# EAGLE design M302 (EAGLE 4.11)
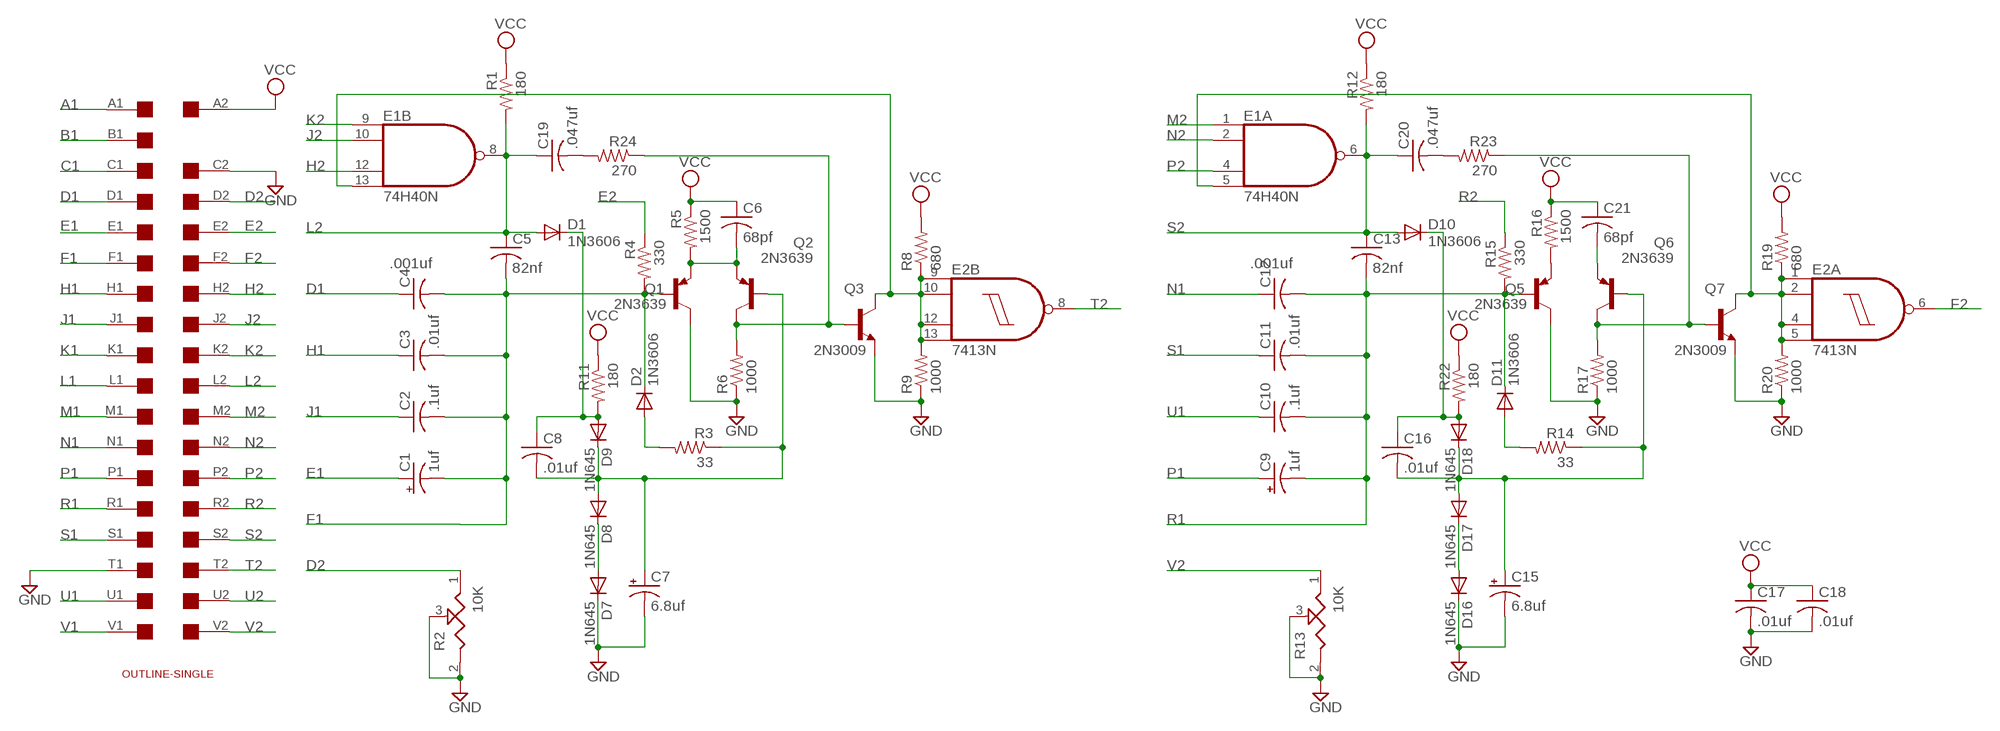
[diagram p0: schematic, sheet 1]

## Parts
C1  1uf  CPOL-USE15-5AXIAL  [E15-5]
C2  .1uf  C-US050-025X075  [C050-025X075]
C3  .01uf  C-US050-025X075  [C050-025X075]
C4  .001uf  C-US050-025X075  [C050-025X075]
C5  82nf  C-US050-025X075  [C050-025X075]
C6  68pf  C-US050-025X075  [C050-025X075]
C7  6.8uf  CPOL-USE15-5AXIAL  [E15-5]
C8  .01uf  C-US050-025X075  [C050-025X075]
C9  1uf  CPOL-USE15-5AXIAL  [E15-5]
C10  .1uf  C-US050-025X075  [C050-025X075]
C11  .01uf  C-US050-025X075  [C050-025X075]
C12  .001uf  C-US050-025X075  [C050-025X075]
C13  82nf  C-US050-025X075  [C050-025X075]
C15  6.8uf  CPOL-USE15-5AXIAL  [E15-5]
C16  .01uf  C-US050-025X075  [C050-025X075]
C17  .01uf  C-US050-025X075  [C050-025X075]
C18  .01uf  C-US050-025X075  [C050-025X075]
C19  .047uf  C-US050-025X075  [C050-025X075]
C20  .047uf  C-US050-025X075  [C050-025X075]
C21  68pf  C-US050-025X075  [C050-025X075]
D1  1N3606  1N4148  [DO35-10]
D2  1N3606  1N4148  [DO35-10]
D7  1N645  1N4148  [DO35-10]
D8  1N645  1N4148  [DO35-10]
D9  1N645  1N4148  [DO35-10]
D10  1N3606  1N4148  [DO35-10]
D11  1N3606  1N4148  [DO35-10]
D16  1N645  1N4148  [DO35-10]
D17  1N645  1N4148  [DO35-10]
D18  1N645  1N4148  [DO35-10]
E1  74H40N  74S20N  [DIL14]
E2  7413N  [DIL14]
Q1  2N3639  2N3637-PNP-TO39-EBC  [TO39]
Q2  2N3639  2N3637-PNP-TO39-EBC  [TO39]
Q3  2N3009  2N3019-NPN-TO39-EBC  [TO39]
Q5  2N3639  2N3637-PNP-TO39-EBC  [TO39]
Q6  2N3639  2N3637-PNP-TO39-EBC  [TO39]
Q7  2N3009  2N3019-NPN-TO39-EBC  [TO39]
R1  180  R-US_0207/10  [0207/10]
R2  10K  POTUS-TRIM  [PT-SPIN]
R3  33  R-US_0207/10  [0207/10]
R4  330  R-US_0207/10  [0207/10]
R5  1500  R-US_0207/10  [0207/10]
R6  1000  R-US_0207/10  [0207/10]
R8  680  R-US_0207/10  [0207/10]
R9  1000  R-US_0207/10  [0207/10]
R11  180  R-US_0207/10  [0207/10]
R12  180  R-US_0207/10  [0207/10]
R13  10K  POTUS-TRIM  [PT-SPIN]
R14  33  R-US_0207/10  [0207/10]
R15  330  R-US_0207/10  [0207/10]
R16  1500  R-US_0207/10  [0207/10]
R17  1000  R-US_0207/10  [0207/10]
R19  680  R-US_0207/10  [0207/10]
R20  1000  R-US_0207/10  [0207/10]
R22  180  R-US_0207/10  [0207/10]
R23  270  R-US_0207/10  [0207/10]
R24  270  R-US_0207/10  [0207/10]
U$1  SINGLE  [EDGE-CON2]
U$2  OUTLINE-SINGLE  [SINGLE]

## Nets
A1: U$1.A1
B1: U$1.B1
C1: U$1.C1
D1: C4.1 U$1.D1
D2: R2.1 U$1.D2
E1: C1.+ U$1.E1
E2: R4.1 U$1.E2
F1: C1.- C2.2 C3.2 C4.2 C5.2 D2.C Q1.2(B) R4.2 U$1.F1
F2: E2.6(A:O) U$1.F2
GND [power]: C7.- C15.- C17.2 C18.2 D7.C D16.C Q1.3(C) Q3.1(E) Q5.3(C) Q7.1(E) R2.2 R2.3 R6.1 R9.1 R13.2 R13.3 R17.1 R20.1 U$1.C2 U$1.T1
H1: C3.1 U$1.H1
H2: E1.12(B:I2) U$1.H2
J1: C2.1 U$1.J1
J2: E1.10(B:I1) U$1.J2
K1: U$1.K1
K2: E1.9(B:I0) U$1.K2
L1: U$1.L1
L2: C5.1 C19.1 D1.A E1.8(B:O) R1.2 U$1.L2
M1: U$1.M1
M2: E1.1(A:I0) U$1.M2
N1: C12.1 U$1.N1
N2: E1.2(A:I1) U$1.N2
N$1: C8.1 D1.C D9.A R11.2
N$2: E1.13(B:I3) E2.9(B:I0) E2.10(B:I1) E2.12(B:I2) E2.13(B:I3) Q3.3(C) R8.1 R9.2
N$3: C6.2 Q1.1(E) Q2.1(E) R5.2
N$4: E1.5(A:I3) E2.1(A:I0) E2.2(A:I1) E2.4(A:I2) E2.5(A:I3) Q7.3(C) R19.1 R20.2
N$5: C7.+ C8.2 D8.A D9.C Q2.2(B) R3.1
N$6: Q6.3(C) Q7.2(B) R17.2 R23.1
N$7: D2.A R3.2
N$8: Q2.3(C) Q3.2(B) R6.2 R24.1
N$9: D7.A D8.C
N$10: Q5.1(E) R16.2
N$11: C21.2 Q6.1(E)
N$12: C15.+ C16.2 D17.A D18.C Q6.2(B) R14.1
N$13: D11.A R14.2
N$14: C19.2 R24.2
N$15: C20.2 R23.2
N$16: C16.1 D10.C D18.A R22.2
N$20: D16.A D17.C
P1: C9.+ U$1.P1
P2: E1.4(A:I2) U$1.P2
R1: C9.- C10.2 C11.2 C12.2 C13.2 D11.C Q5.2(B) R15.2 U$1.R1
R2: R15.1 U$1.R2
S1: C11.1 U$1.S1
S2: C13.1 C20.1 D10.A E1.6(A:O) R12.2 U$1.S2
T2: E2.8(B:O) U$1.T2
U1: C10.1 U$1.U1
U2: U$1.U2
V1: U$1.V1
V2: R13.1 U$1.V2
VCC [power]: C6.1 C17.1 C18.1 C21.1 R1.1 R5.1 R8.2 R11.1 R12.1 R16.1 R19.2 R22.1 U$1.A2
Unconnected: U$1.B2

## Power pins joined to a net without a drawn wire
GND: E1.7(P:GND) E2.7(P:GND)
VCC: E1.14(P:VCC) E2.14(P:VCC)

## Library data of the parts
C1 C7 C9 C15 = rcl:CPOL-US: POLARIZED CAPACITOR, American symbol
C2-C6 C8 C10-C13 C16-C21 = rcl:C-US: CAPACITOR, American symbol
D1 D2 D7-D11 D16-D18 = diode:1N4148: DIODE
E1 = 74xx-us:74*20: Dual 4-input NAND gate
E2 = 74xx-us:74*13: Dual 4-input NAND schmitt trigger
Q1 Q2 Q5 Q6 = transistor:*-PNP-: PNP Transistror
Q3 Q7 = transistor:*-NPN-: NPN Transistror
R1 R3-R6 R8 R9 R11 R12 R14-R17 R19 R20 R22-R24 = rcl:R-US_: RESISTOR, American symbol
R2 R13 = discrete:POTUS-TRIM
U$1 = dec-con:SINGLE: Single-Height DEC board
U$2 = dec-con:OUTLINE-*: Board outlines for DEC boards.

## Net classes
1 power: width 0.508 mm, drill 0.508 mm

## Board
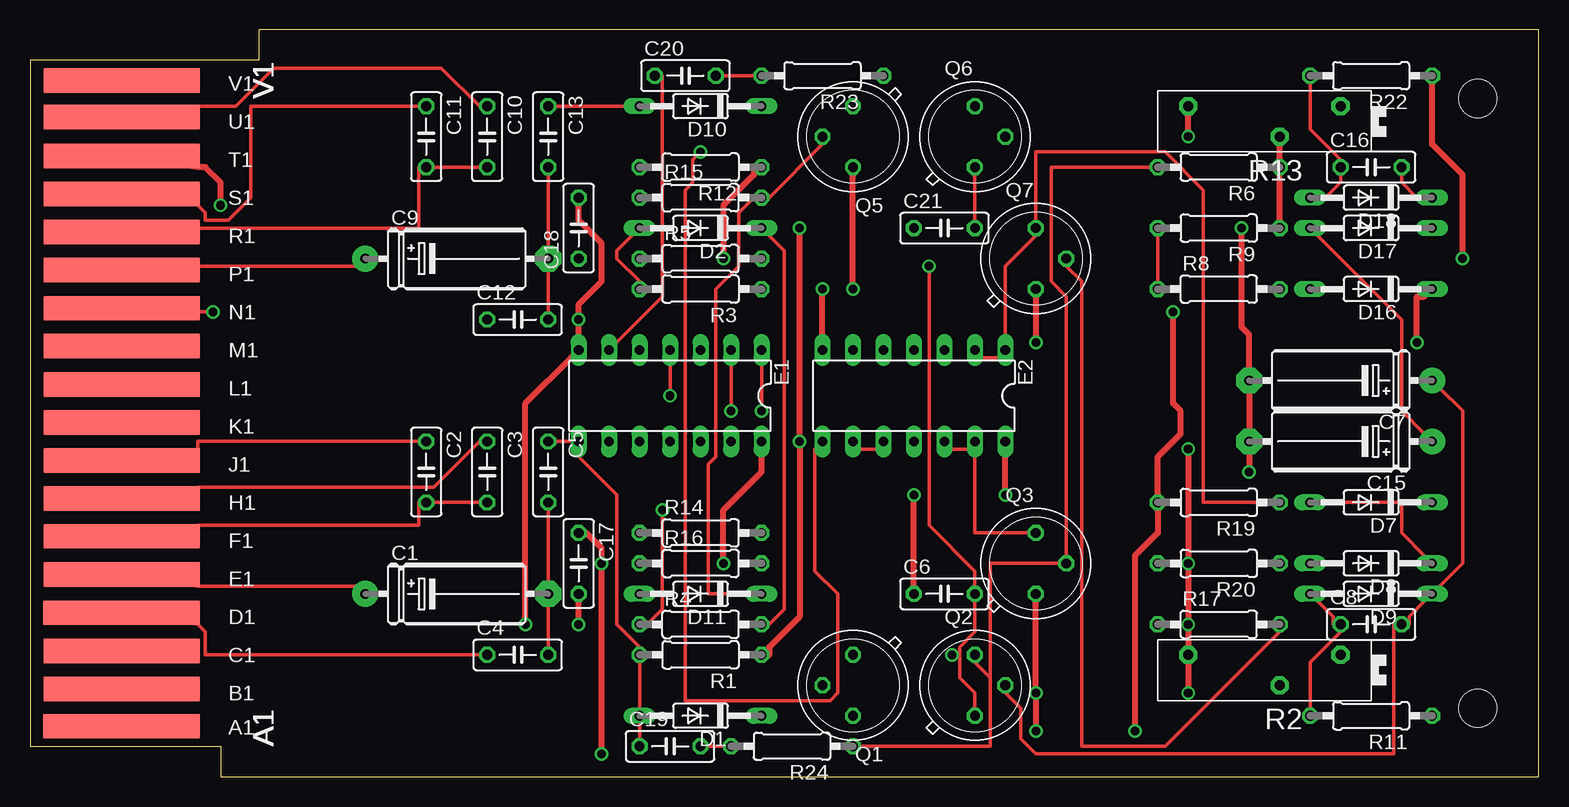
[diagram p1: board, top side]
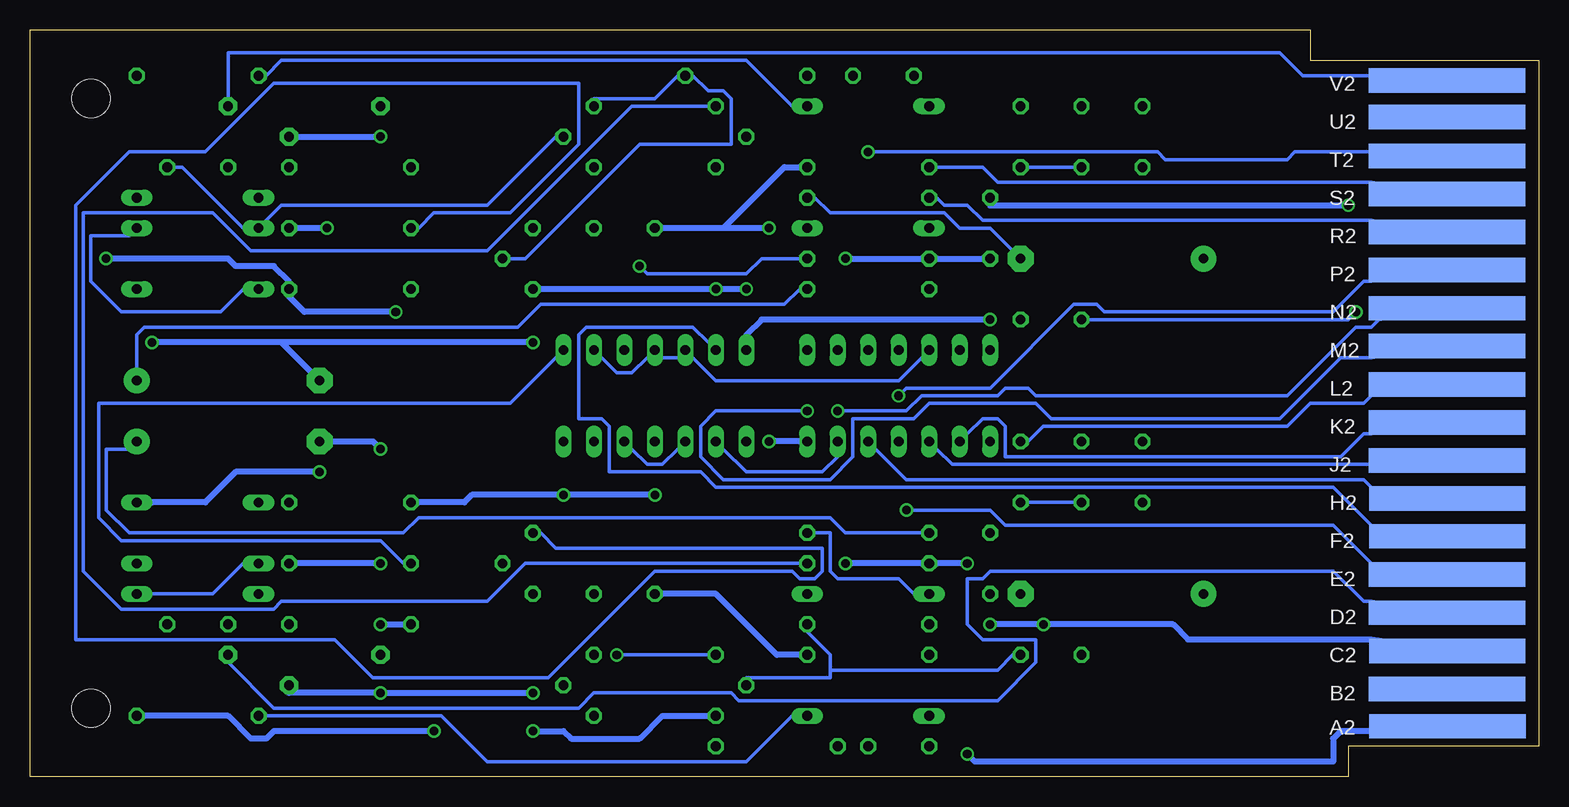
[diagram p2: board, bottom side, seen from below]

Size 125.73 x 62.23 mm. Coordinates in mm from the lower left corner, seen from the top.
Copper layers (1*16): Top 0.035mm / dielectric 1.5mm / Bottom 0.035mm
Design rules "10mils": minimum track width 12mil, minimum drill 28mil, track to track 10mil, track to pad 10mil, pad to pad 10mil, via to via 10mil, smd to smd 10mil, copper to edge 40mil, drill to drill 10mil, minimum pad ring 10mil, minimum via ring 8mil, stop-mask expansion 0mil, vias tented up to drill 0mil, thermal gap 10mil

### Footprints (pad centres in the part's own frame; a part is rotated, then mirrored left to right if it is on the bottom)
E15-5 = drill 0.813 pad 2.159 round: + -7.62,0 | drill 0.813 pad 2.159 octagon: - 7.62,0
C050-025X075 = drill 0.813 octagon: 1 -2.54,0; 2 2.54,0
DO35-10 = drill 0.813 long: A 5.08,0; C -5.08,0
DIL14 = drill 0.813 long: 1 -7.62,-3.81; 2 -5.08,-3.81; 3 -2.54,-3.81; 4 0,-3.81; 5 2.54,-3.81; 6 5.08,-3.81; 7 7.62,-3.81; 8 7.62,3.81; 9 5.08,3.81; 10 2.54,3.81; 11 0,3.81; 12 -2.54,3.81; 13 -5.08,3.81; 14 -7.62,3.81
TO39 = drill 0.813 octagon: 1 0,-2.54; 2 2.54,0; 3 0,2.54
0207/10 = drill 0.813 octagon: 1 -5.08,0; 2 5.08,0
PT-SPIN = drill 0.813 pad 1.524 octagon: 1 -6.35,-1.27; 2 6.35,-1.27; 3 -1.27,1.27
EDGE-CON2 = smd 13.017 x 2.032: A1 7.633,4.207; B1 7.639,7.327; C1 7.636,10.489; D1 7.633,13.665; E1 7.642,16.84; F1 7.642,20.041; H1 7.642,23.19; J1 7.642,26.34; K1 7.642,29.515; L1 7.642,32.69; M1 7.642,35.89; N1 7.642,39.04; P1 7.642,42.24; R1 7.642,45.39; S1 7.642,48.565; T1 7.642,51.74; U1 7.642,54.966; V1 7.642,58.026 | smd 13.017 x 2.032 bottom: A2 7.614,4.207; B2 7.642,7.328; C2 7.617,10.49; D2 7.642,13.665; E2 7.642,16.84; F2 7.617,20.041; H2 7.617,23.19; J2 7.642,26.34; K2 7.642,29.515; L2 7.642,32.69; M2 7.642,35.89; N2 7.642,39.04; P2 7.642,42.24; R2 7.642,45.39; S2 7.642,48.565; T2 7.642,51.74; U2 7.642,54.966; V2 7.642,58.026
SINGLE = hole 3.175: 120.65,56.515; 120.65,5.715

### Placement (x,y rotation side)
C1  35.56,15.24 0 top
C2  33.02,25.4 270 top
C3  38.1,25.4 270 top
C4  40.64,10.16 0 top
C5  43.18,25.4 270 top
C6  76.2,15.24 0 top
C7  109.22,33.02 180 top
C8  111.76,12.7 0 top
C9  35.56,43.18 0 top
C10  38.1,53.34 270 top
C11  33.02,53.34 270 top
C12  40.64,38.1 0 top
C13  43.18,53.34 270 top
C15  109.22,27.94 180 top
C16  111.76,50.8 0 top
C17  45.72,17.78 270 top
C18  45.72,45.72 90 top
C19  53.34,2.54 0 top
C20  54.61,58.42 0 top
C21  76.2,45.72 0 top
D1  55.88,5.08 180 top
D2  55.88,45.72 180 top
D7  111.76,22.86 180 top
D8  111.76,17.78 180 top
D9  111.76,15.24 180 top
D10  55.88,55.88 180 top
D11  55.88,15.24 180 top
D16  111.76,40.64 180 top
D17  111.76,45.72 180 top
D18  111.76,48.26 180 top
E1  53.34,31.75 180 top
E2  73.66,31.75 180 top
Q1  68.58,7.62 180 top
Q2  78.74,7.62 0 top
Q3  83.82,17.78 0 top
Q5  68.58,53.34 180 top
Q6  78.74,53.34 0 top
Q7  83.82,43.18 0 top
R1  55.88,10.16 180 top
R2  102.87,8.89 180 top
R3  55.88,40.64 180 top
R4  55.88,12.7 0 top
R5  55.88,43.18 0 top
R6  99.06,50.8 180 top
R8  99.06,40.64 0 top
R9  99.06,45.72 180 top
R11  111.76,5.08 180 top
R12  55.88,50.8 180 top
R13  102.87,54.61 180 top
R14  55.88,20.32 0 top
R15  55.88,48.26 0 top
R16  55.88,17.78 0 top
R17  99.06,12.7 0 top
R19  99.06,22.86 180 top
R20  99.06,17.78 180 top
R22  111.76,58.42 180 top
R23  66.04,58.42 180 top
R24  63.5,2.54 180 top
U$1  0,0 0 top
U$2  0,0 0 top

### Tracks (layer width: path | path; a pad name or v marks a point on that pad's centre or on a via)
D1
  Top 0.305: C4.1 37.47,10.16 14.61,10.16 14.61,12.06 13.97,12.7 U$1.D1
D2
  Bottom 0.305: R2.1 109.22,9.53 105.41,5.71 80.01,5.71 78.74,6.99 67.31,6.99 66.68,6.35 45.09,6.35 41.91,9.53 41.91,11.43 46.36,11.43 47.63,12.7 47.63,16.51 46.36,16.51 45.72,17.14 17.15,17.14 14.61,14.61 13.97,14.61 U$1.D2
E1
  Top 0.305: C1.+ 27.31,15.88 13.97,15.88 U$1.E1
E2  (via drill 0.71)
  Top 0.305: v52.71,22.23 52.71,13.97 51.44,12.7 R4.1
  Bottom 0.305: v52.71,22.23 45.72,22.23 44.45,20.95 17.15,20.95 13.97,17.78 U$1.E2
F1
  Top 0.305: C4.2 43.18,10.79 43.18,14.61 C1.- 43.18,15.88 43.18,22.23 C5.2 | C3.2 37.47,22.86 33.66,22.86 C2.2 32.39,22.86 32.39,20.95 13.97,20.95 U$1.F1 | D2.C 61.6,45.09 62.87,43.81 62.87,13.97 61.6,12.7 R4.2
  Bottom 0.305: C5.2 42.55,22.86 38.74,22.86 C3.2 | 59.06,8.89 59.06,8.26 66.04,8.26 Q1.2 | 59.06,8.89 59.06,10.16 60.96,12.06 R4.2 | 59.06,8.89 45.09,8.89 43.82,10.16 C4.2
F2
  Bottom 0.305: E2.6 69.22,36.2 70.49,37.47 79.38,37.47 80.01,36.83 80.01,29.84 78.11,29.84 77.47,29.21 77.47,25.4 69.85,25.4 68.58,24.13 17.15,24.13 13.97,20.95 U$1.F2
GND  (via drill 0.71)
  Top 0.508: v96.52,6.99 96.52,9.53 R2.2 96.52,10.79 v96.52,12.7 v96.52,17.78 v96.52,27.3 | v83.82,3.81 v83.82,6.99 83.82,14.61 Q3.1 | v66.04,40.64 66.04,36.83 E2.7 | v68.58,40.64 68.58,50.16 Q5.3 | v101.6,25.4 101.6,27.3 C15.- 101.6,28.57 101.6,32.38 C7.- 101.6,33.66 101.6,36.83 100.97,37.47 v100.97,45.72 | R9.1 104.14,46.35 104.14,50.16 R6.1 104.14,51.44 104.14,52.7 R13.3 | v96.52,53.34 96.52,55.24 R13.2 | v115.57,36.2 115.57,40.01 116.21,40.01 D16.C | v83.82,36.2 83.82,40.01 Q7.1 | v45.72,12.7 45.72,14.61 C17.2 | v15.88,47.62 15.88,49.53 14.61,50.8 13.97,50.8 U$1.T1 | C18.2 45.72,47.62 45.72,46.35 47.63,44.45 47.63,41.27 45.72,39.37 v45.72,38.1 45.72,36.83 E1.7 45.09,34.92 41.28,31.11 v41.28,12.7
  Bottom 0.508: v96.52,12.7 94.62,12.7 R17.1 | v96.52,17.78 103.51,17.78 R20.1 | R2.3 104.14,6.99 v96.52,6.99 v83.82,6.99 | v83.82,3.81 81.28,3.81 80.65,3.17 74.93,3.17 73.03,5.08 69.22,5.08 Q1.3 | v66.04,40.64 v68.58,40.64 83.19,40.64 Q7.1 | v101.6,25.4 108.59,25.4 111.13,22.86 115.57,22.86 D7.C | v96.52,53.34 103.51,53.34 R13.3 | 104.78,36.2 v115.57,36.2 | 104.78,36.2 102.24,33.66 C7.- | v100.97,45.72 103.51,45.72 R9.1 | v83.82,36.2 104.78,36.2 | v96.52,27.3 97.16,27.94 100.97,27.94 C15.- | v45.72,12.7 v41.28,12.7 30.48,12.7 29.21,11.43 13.97,11.43 U$1.C2 | v15.88,47.62 45.72,47.62 C18.2 | v45.72,38.1 64.77,38.1 66.04,36.83 E2.7
H1
  Top 0.305: C3.1 37.47,27.94 33.66,24.13 13.97,24.13 U$1.H1
H2
  Bottom 0.305: E1.12 55.25,27.3 52.71,24.77 14.61,24.77 13.97,24.13 U$1.H2
J1
  Top 0.305: C2.1 32.39,27.94 13.97,27.94 13.97,27.3 U$1.J1
J2
  Bottom 0.305: E1.10 50.17,27.3 48.9,26.04 13.97,26.04 U$1.J2
K2
  Bottom 0.305: E1.9 47.63,28.57 46.36,29.84 45.09,29.84 44.45,29.21 44.45,26.67 16.51,26.67 14.61,28.57 13.97,28.57 U$1.K2
L2
  Top 0.305: C5.1 43.82,27.94 45.09,27.94 E1.8 45.72,26.67 48.9,23.5 48.9,12.7 50.8,10.79 R1.2 50.8,9.53 50.8,5.71 D1.A 50.8,4.45 50.8,3.17 C19.1
  Bottom 0.305: U$1.L2 13.97,31.75 14.61,31.11 19.05,31.11 20.96,29.21 41.28,29.21 42.55,27.94 C5.1
M2  (via drill 0.71)
  Top 0.305: v60.96,30.48 60.96,34.29 E1.1
  Bottom 0.305: v60.96,30.48 68.58,30.48 69.85,29.21 69.85,26.67 67.95,24.77 59.06,24.77 57.15,26.67 57.15,29.84 52.07,29.84 50.8,31.11 41.91,31.11 40.64,29.84 21.59,29.84 16.51,34.92 13.97,34.92 U$1.M2
N1  (via drill 0.71)
  Top 0.305: v15.24,38.73 13.97,38.73 U$1.N1
  Bottom 0.305: v15.24,38.73 15.88,38.1 37.47,38.1 C12.1
N2  (via drill 0.71)
  Top 0.305: v58.42,30.48 58.42,34.29 E1.2
  Bottom 0.305: v58.42,30.48 52.71,30.48 51.44,31.75 45.09,31.75 44.45,32.38 42.55,32.38 41.91,31.75 20.96,31.75 15.24,37.47 13.97,37.47 13.34,38.1 U$1.N2
N$1
  Top 0.305: D9.A 107.32,14.61 108.59,13.34 108.59,12.7 C8.1 109.22,12.06 106.68,9.53 106.68,5.71 R11.2
  Bottom 0.305: D1.C 62.23,5.08 66.04,1.27 87.63,1.27 91.44,5.08 106.05,5.08 R11.2
N$2
  Top 0.305: E2.10 70.49,27.3 69.22,27.3 E2.9 | R8.1 93.98,41.27 93.98,45.09 R9.2 | E2.12 76.84,27.3 78.11,27.3 E2.13 78.74,26.67 78.74,20.32 83.19,20.32 Q3.3
  Bottom 0.305: E1.13 58.42,26.67 59.69,25.4 66.04,25.4 67.95,27.3 E2.9 | R9.2 93.35,45.72 92.08,46.99 85.73,46.99 80.01,52.7 80.01,57.78 105.41,57.78 111.13,52.07 117.48,52.07 121.92,47.62 121.92,11.43 100.33,11.43 97.16,8.26 82.55,8.26 73.66,17.14 62.23,17.14 61.6,16.51 60.33,16.51 59.69,17.14 59.69,19.05 81.92,19.05 83.19,20.32 Q3.3 | E2.10 71.76,27.3 73.03,26.04 74.3,26.04 75.57,27.3 E2.12
N$3  (via drill 0.71)
  Top 0.305: 77.47,10.16 77.47,8.26 78.74,6.99 78.74,5.71 Q2.1 | 77.47,10.16 77.47,10.79 78.74,12.06 78.74,14.61 C6.2 78.74,15.88 78.74,17.14 74.93,20.95 v74.93,42.55 | v76.84,10.16 77.47,10.16
  Bottom 0.305: v76.84,10.16 69.22,10.16 Q1.1 | v74.93,42.55 74.3,41.91 66.04,41.91 64.77,43.18 61.6,43.18 R5.2
N$4
  Top 0.305: E2.2 79.38,34.92 80.65,34.92 E2.1 81.28,36.83 81.28,42.55 83.82,45.09 Q7.3 83.82,46.35 83.82,52.07 94.62,52.07 97.79,48.9 97.79,22.86 103.51,22.86 R19.1
  Bottom 0.305: E1.5 51.44,34.92 53.34,33.02 68.58,33.02 70.49,34.92 E2.5 71.76,34.92 73.03,34.92 E2.4 74.3,34.92 75.57,33.66 76.84,33.66 78.11,34.92 E2.2 | R20.2 94.62,17.78 96.52,19.68 118.11,19.68 120.02,21.59 120.02,31.11 85.73,31.11 81.92,34.92 E2.1
N$5
  Top 0.305: Q2.2 81.28,6.99 82.55,5.71 82.55,3.17 83.82,1.91 113.67,1.91 113.67,12.7 C8.2 114.94,12.7 114.94,13.34 116.21,14.61 D9.C 117.48,15.88 119.38,17.78 119.38,30.48 117.48,32.38 C7.+
  Bottom 0.305: D8.A 107.95,17.78 110.49,15.24 115.57,15.24 D9.C | R3.1 61.6,40.64 62.87,39.37 83.19,39.37 85.09,37.47 116.21,37.47 116.84,36.83 116.84,33.66 C7.+
N$6
  Top 0.305: R17.2 104.14,12.06 94.62,2.54 87.63,2.54 87.63,41.27 86.36,42.55 Q7.2
  Bottom 0.305: Q6.3 78.74,56.52 73.66,56.52 71.76,58.42 R23.1 70.49,58.42 69.22,57.15 67.95,57.15 67.31,56.52 67.31,52.7 74.93,52.7 84.46,43.18 85.73,43.18 Q7.2
N$7
  Top 0.305: R3.2 50.8,41.27 48.9,43.18 48.9,43.81 50.17,45.09 D2.A
N$8
  Top 0.305: 80.01,8.26 80.01,2.54 69.22,2.54 R24.1 | 80.01,8.26 78.74,9.53 Q2.3 | 80.01,8.26 80.01,17.78 85.73,17.78 Q3.2 86.36,18.41 86.36,40.01 85.09,41.27 85.09,50.8 93.35,50.8 R6.2
N$9
  Top 0.305: D7.A 107.95,22.86 114.3,22.86 114.3,20.32 116.21,18.41 D8.C
N$10
  Bottom 0.305: R16.2 61.6,17.78 84.46,17.78 87.63,14.61 104.78,14.61 105.41,13.97 118.11,13.97 121.29,17.14 121.29,46.99 110.49,46.99 107.32,43.81 87.63,43.81 75.57,55.88 69.22,55.88 Q5.1
N$11
  Top 0.305: C21.2 78.74,46.35 78.74,50.16 Q6.1
N$12
  Top 0.305: D18.C 115.57,48.26 114.3,49.53 114.3,50.16 C16.2 | D17.A 107.32,45.09 114.3,38.1 114.3,30.48 116.21,28.57 C15.+
  Bottom 0.305: C16.2 113.67,50.8 113.03,50.8 107.95,45.72 D17.A 106.05,46.35 104.78,47.62 87.63,47.62 81.92,53.34 Q6.2 | R14.1 51.44,20.32 57.79,20.32 59.06,21.59 93.35,21.59 94.62,20.32 117.48,20.32 119.38,22.23 119.38,27.3 117.48,27.3 C15.+
N$13
  Bottom 0.305: D11.A 52.07,15.24 53.34,16.51 58.42,16.51 59.06,17.14 59.06,20.32 60.33,20.32 R14.2
N$14
  Top 0.305: C19.2 56.52,2.54 57.79,2.54 R24.2
N$15
  Top 0.305: C20.2 57.79,58.42 60.33,58.42 R23.2
N$16
  Top 0.305: D18.A 107.95,48.26 109.22,49.53 109.22,50.16 C16.1 109.22,51.44 106.68,53.98 106.68,57.78 R22.2
  Bottom 0.305: D10.C 62.23,55.88 66.04,59.69 104.78,59.69 106.05,58.42 R22.2
N$20
  Bottom 0.305: D16.A 107.95,40.64 109.86,38.73 118.11,38.73 120.65,41.27 120.65,45.09 117.48,45.09 D17.C
P1
  Top 0.305: C9.+ 27.31,42.55 13.97,42.55 U$1.P1
P2  (via drill 0.71)
  Top 0.305: v53.34,31.75 53.34,34.29 E1.4
  Bottom 0.305: v53.34,31.75 52.71,32.38 45.72,32.38 38.74,39.37 36.83,39.37 36.2,38.73 17.15,38.73 14.61,41.27 13.97,41.27 U$1.P2
R1
  Top 0.305: C12.2 43.18,38.73 43.18,42.55 C9.- 43.18,43.81 43.18,50.16 C13.2 | C10.2 37.47,50.8 33.66,50.8 C11.2 32.39,50.8 32.39,45.72 13.97,45.72 U$1.R1 | D11.C 59.69,15.24 56.52,15.24 56.52,26.04 57.15,26.67 57.15,40.64 59.06,42.55 59.06,46.99 60.33,48.26 R15.2 61.6,48.26 66.04,52.7 Q5.2
  Bottom 0.305: C13.2 42.55,50.8 38.74,50.8 C10.2 | C9.- 43.82,43.81 45.72,45.72 48.26,45.72 49.53,46.99 59.06,46.99 60.33,48.26 R15.2
R2
  Bottom 0.305: R15.1 50.17,48.26 49.53,47.62 47.63,47.62 46.36,46.35 13.97,46.35 U$1.R2
S1
  Top 0.305: C11.1 32.39,55.88 18.42,55.88 18.42,48.26 16.51,46.35 14.61,46.35 14.61,46.99 13.97,47.62 U$1.S1
S2
  Top 0.305: C13.1 43.82,55.88 49.53,55.88 D10.A 52.07,55.88 52.71,55.88 | 52.71,55.88 52.71,58.42 C20.1 | 52.71,50.8 52.71,55.88 | 52.71,50.8 52.71,40.01 48.9,36.2 E1.6 | 52.71,50.8 51.44,50.8 R12.2
  Bottom 0.305: U$1.S2 13.97,49.53 45.09,49.53 46.36,50.8 50.17,50.8 R12.2
T2  (via drill 0.71)
  Top 0.305: v55.88,52.07 55.25,51.44 55.25,49.53 54.61,48.9 54.61,6.35 66.68,6.35 67.31,6.99 67.31,15.24 65.41,17.14 65.41,27.3 E2.8
  Bottom 0.305: v55.88,52.07 31.75,52.07 31.12,51.44 20.96,51.44 20.32,52.07 13.97,52.07 U$1.T2
U1
  Top 0.305: C10.1 37.47,55.88 34.29,59.05 20.32,59.05 17.15,55.88 13.97,55.88 U$1.U1
V2
  Bottom 0.305: R13.1 109.22,56.52 109.22,60.33 21.59,60.33 19.69,58.42 13.97,58.42 U$1.V2
VCC  (via drill 0.71)
  Top 0.508: v47.63,1.91 v47.63,17.78 47.63,19.05 46.36,20.32 C17.1 | v57.79,17.78 57.79,22.23 60.96,25.4 60.96,26.67 E1.14 | v57.79,43.18 57.79,47.62 60.33,50.16 60.33,50.8 R12.1 | v81.28,23.5 81.28,26.67 E2.14 | v92.08,3.81 92.08,18.41 93.98,20.32 93.98,22.23 R19.2 93.98,23.5 93.98,26.67 95.89,28.57 95.89,30.48 95.25,31.11 v95.25,38.73 | v119.38,43.18 119.38,50.16 116.84,52.7 116.84,57.78 R22.1 | v73.66,23.5 73.66,15.88 C6.1 | v64.14,45.72 v64.14,27.94 64.14,13.34 61.6,10.79 61.6,10.16 R1.1
  Bottom 0.508: v47.63,1.91 46.99,1.27 17.15,1.27 17.15,3.17 16.51,3.81 13.97,3.81 U$1.A2 | v47.63,17.78 50.17,17.78 R16.1 51.44,17.78 v57.79,17.78 | C18.1 46.36,43.18 50.17,43.18 R5.1 51.44,43.18 v57.79,43.18 | 67.95,45.72 73.03,45.72 C21.1 | 67.95,45.72 62.87,50.8 61.6,50.8 R12.1 | R1.1 61.6,10.16 63.5,10.16 68.58,15.24 73.03,15.24 C6.1 | R19.2 93.35,22.86 89.54,22.86 88.9,23.5 v81.28,23.5 v73.66,23.5 | v92.08,3.81 105.41,3.81 106.05,3.17 107.32,3.17 109.22,5.08 116.21,5.08 R11.1 | v95.25,38.73 102.87,38.73 104.14,40.01 R8.2 104.14,41.27 105.41,42.55 108.59,42.55 109.22,43.18 v119.38,43.18 | v64.14,45.72 67.95,45.72 | v64.14,27.94 61.6,27.94 E1.14

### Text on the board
tNames: V1 | V1 | V1 | V1 | V1 | V1 | V1 | V1 | V1 | V1 | V1 | V1 | V1 | V1 | V1 | V1 | V1 | V1 | V1 | V1 | V1 | V1 | V1 | V1 | V1 | V1 | V1 | V1 | V1 | V1 | V1 | V1 | A1 | A1 | A1 | A1 | A1 | A1 | A1 | A1 | A1 | A1 | A1 | A1 | A1 | A1 | A1 | A1 | A1 | A1 | A1 | A1 | A1 | A1 | A1 | A1 | A1 | A1 | A1 | A1 | A1 | A1 | A1 | A1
